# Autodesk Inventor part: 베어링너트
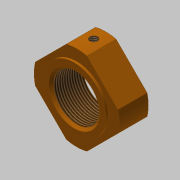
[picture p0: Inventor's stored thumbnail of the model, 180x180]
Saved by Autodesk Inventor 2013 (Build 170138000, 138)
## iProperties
Created: 2019-05
Part Number: 베어링너트
Material: 스테인리스강
Document SubType Name: Modeling
Designer: mduedu
Density: 1 g/cm^3
d0: 35.000 mm
d1: 12.000 mm
d2: 0.00 deg
d3: 30.000 mm
d5: 30.000 mm
d7: 0.00 deg
d8: 26.000 mm
d9: 1.000 mm
d10: 0.00 deg
d20: 1.000 mm
d31: 5.000 mm
Author: mduedu
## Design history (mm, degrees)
sketch "스케치1"
  geometry: C1 r 17.5 at (0, 0); 1 further point
  constraints: 1 centre point, 1 coincident
  dimensions: "d0" = 35 diameter of C1
extrude "돌출1" new body sketch "스케치1" distance "d1" = 12; taper "d2" = 0 deg
sketch "스케치2"
  geometry: L1 (-21.213, 0)-(0, 21.213); L2 (0, 21.213)-(21.213, 0); L3 (21.213, 0)-(0, -21.213); L4 (0, -21.213)-(-21.213, 0); L5 (-21.213, 0)-(21.213, 0); L6 (0, 21.213)-(0, -21.213); 1 further point
  constraints: 12 end point, 2 midpoint, 2 parallel, 1 perpendicular, 1 vertical
  dimensions: "d3" = 30 distance of L1.end L2.end; "d5" = 30 distance of L2.end L3.end
extrude "돌출2" sketch "스케치2" stored distance "d6" = 12; taper "d7" = 0 deg
sketch "스케치3"
  geometry: C1 r 13 at (0, 0); 1 further point
  constraints: 1 centre point, 1 coincident
  dimensions: "d8" = 26 diameter of C1
extrude "돌출3" join sketch "스케치3" distance "d9" = 1; taper "d10" = 0 deg
hole "구멍1" diameter "d13" = 18.917; stored, may be unused: countersink angle "d17" = 90 deg, drill point angle "d19" = 118 deg; dims "d11" = 10, "d12" = 10, "d14" = 6, "d15" = 4, "d16" = 2, "d18" = 8
chamfer "모따기1" distance "d20" = 1; stored, may be unused: second distance "d21" = 2, angle "d22" = 45 deg
node "작업 평면1"
sketch "스케치5"
  geometry: L1 (-4.233, 0)-(4.233, 0) reference; 3 further points
  constraints: 1 midpoint, 1 vertical alignment
  dimensions: "d31" = 5 distance from line of point (0, 5) L1
hole "구멍3" sketch "스케치5" at (0, 5) diameter "d32" = 3.242; stored, may be unused: countersink angle "d36" = 90 deg, drill point angle "d38" = 118 deg; dims "d33" = 6, "d34" = 4, "d35" = 2, "d37" = 8
node "솔리드1"
